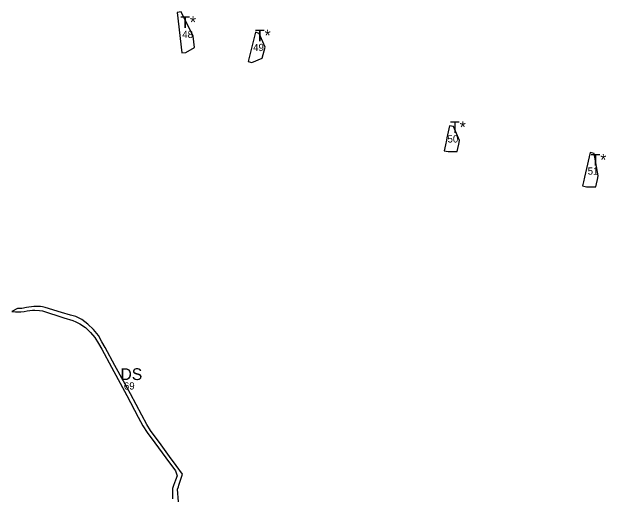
# Model space of a CAD drawing. Extents: x -535435 to -532834, y -1165802 to -1163866.
# Drawn here: x -534829 to -534171, y -1164698 to -1164165 of the extents above; entities that cross this region are included whole.
import ezdxf

# ---------------------------------------------------------------- set-up
doc = ezdxf.new("R2010")
doc.units = 0
for name, color, linetype in [('Level 23', 7, 'Continuous'), ('Level 5', 7, 'Continuous'), ('Level 61', 7, 'Continuous')]:
    doc.layers.add(name, color=color, linetype=linetype)

msp = doc.modelspace()

# ---------------------------------------------------------------- linework, layer by layer
at = {"layer": 'Level 23'}
for points in [[(-534641.46, -1164165.28), (-534645.78, -1164165.89), (-534640.71, -1164210.58), (-534636.34, -1164210.08), (-534626.89, -1164204.68), (-534628.3, -1164192.26), (-534641.46, -1164165.28)], [(-534559.25, -1164187.61), (-534567.49, -1164220.26), (-534563.23, -1164221.34), (-534551.69, -1164216.52), (-534548.63, -1164204.4), (-534555.08, -1164189.08), (-534559.25, -1164187.61)]]:
    msp.add_lwpolyline(points, dxfattribs=at)
for points in [[(-534350.52, -1164318.78), (-534346.22, -1164319.71), (-534335.99, -1164319.7), (-534335.29, -1164316.44), (-534334.23, -1164311.51), (-534333.37, -1164307.48), (-534340.29, -1164292.04), (-534344.59, -1164291.11), (-534347.47, -1164304.55), (-534347.99, -1164306.99), (-534349.08, -1164312.05)], [(-534182.72, -1164358.73), (-534181.97, -1164355.44), (-534180.86, -1164350.56), (-534179.95, -1164346.54), (-534184.57, -1164321.84), (-534188.86, -1164320.87), (-534193.93, -1164343.09), (-534195.06, -1164348.06), (-534196.17, -1164352.93), (-534197.24, -1164357.62), (-534192.95, -1164358.6)]]:
    msp.add_lwpolyline(points, close=True, dxfattribs=at)
at = {"layer": 'Level 5'}
for points in [[(-534644.02, -1164688.26), (-534641.28, -1164679.59), (-534639.91, -1164676.11), (-534647.09, -1164666.49), (-534654.21, -1164656.79), (-534663.7, -1164643.95), (-534675.38, -1164627.9), (-534679.39, -1164621.17), (-534684.96, -1164611.11), (-534697.59, -1164587.58), (-534714.73, -1164556.06), (-534725.76, -1164536.1), (-534729.11, -1164529.78), (-534733.1, -1164523.11), (-534738.48, -1164516.32), (-534744.63, -1164510.37), (-534751.32, -1164505.21), (-534758.1, -1164502.08), (-534763.83, -1164500.67), (-534774.03, -1164497.36), (-534791.93, -1164491.89), (-534795.04, -1164491.15), (-534797.22, -1164490.89), (-534799.19, -1164490.8), (-534804.68, -1164491.01), (-534812.44, -1164492.04), (-534817.87, -1164493.05), (-534820.49, -1164493.14), (-534822.73, -1164493.03), (-534828.8, -1164496.42), (-534824.62, -1164496.84), (-534821.8, -1164496.9), (-534819, -1164496.79), (-534815.12, -1164496.42), (-534811.89, -1164495.83), (-534806.11, -1164495), (-534803.32, -1164494.85), (-534798.38, -1164495.21), (-534794.97, -1164495.87), (-534771.15, -1164503.33), (-534761.23, -1164506.36), (-534758.01, -1164507.73), (-534753.52, -1164510.08), (-534747.52, -1164514.09), (-534741.75, -1164519.51), (-534737.08, -1164525.16), (-534732.79, -1164531.83), (-534729.34, -1164538.04), (-534718.52, -1164558.02), (-534701.71, -1164589.35), (-534688.97, -1164613.29), (-534683.79, -1164622.82), (-534679.18, -1164630.14), (-534670.74, -1164641.72), (-534658.27, -1164658.05), (-534647.63, -1164672.43), (-534645.85, -1164677.96), (-534647.9, -1164682.84), (-534649.92, -1164688.58), (-534650.97, -1164692.25), (-534651.25, -1164703.41)], [(-534644.26, -1164706.72), (-534645.38, -1164692.75), (-534644.56, -1164690.05), (-534644.02, -1164688.26)]]:
    msp.add_lwpolyline(points, dxfattribs=at)

# ---------------------------------------------------------------- texts
at = {"layer": 'Level 23'}
for p in [(-534642.4, -1164183.17), (-534559.81, -1164197.84), (-534343.88, -1164299.18), (-534188.39, -1164335.28)]:
    msp.add_text('T*', height=13, dxfattribs=at).set_placement(p)
at = {"layer": 'Level 5'}
msp.add_text('DS', height=13, dxfattribs=at).set_placement((-534708.67, -1164572.18))
at = {"layer": 'Level 61'}
for s, p in [('48', (-534640.26, -1164194.19)), ('49', (-534561.85, -1164208.6)), ('50', (-534346.78, -1164309.67)), ('51', (-534191.68, -1164345.14)), ('69', (-534704.85, -1164582.69))]:
    msp.add_text(s, height=8, dxfattribs=at).set_placement(p)

doc.saveas('drawing.dxf')
